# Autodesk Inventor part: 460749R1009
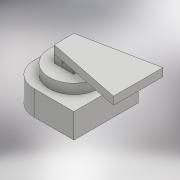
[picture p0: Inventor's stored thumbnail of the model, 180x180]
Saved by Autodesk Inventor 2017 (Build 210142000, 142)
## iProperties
Created: 2016-07
Part Number: 460749R1009
Material: Generic
Document SubType Name: Modeling
Designer: Polytech
Density: 1 g/cm^3
Appearance: Default
Author: Polytech
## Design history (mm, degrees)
sketch "Sketch1"
  geometry: C1 r 23 at (0, 0); 1 further point
  constraints: 1 centre point, 1 coincident
  dimensions: "d0" = 46 diameter of C1
extrude "Extrusion1" new body sketch "Sketch1" distance "d1" = 18; taper "d2" = 0 deg
sketch "Sketch2"
  geometry: L1 (-11.75, 48.75)-(48.75, 48.75); L2 (48.75, 48.75)-(48.75, -48.75); L3 (48.75, -48.75)-(-11.75, -48.75); L4 (-48.75, -11.75)-(-48.75, 11.75); L5 (-48.75, 48.75)-(48.75, -48.75); L6 (48.75, 48.75)-(-48.75, -48.75); A1 r 37 centre (-11.75, 11.75) between (-11.75, 48.75) and (-48.75, 11.75); A2 r 37 centre (-11.75, -11.75) between (-48.75, -11.75) and (-11.75, -48.75); 1 further point
  constraints: 12 end point, 4 point on circle, 4 point on line, 4 tangent, 2 centre point, 2 midpoint, 2 parallel, 1 equal radius, 1 horizontal, 1 perpendicular
  dimensions: "d3" = 97.5 distance of L2.end L6.end; "d4" = 97.5 distance of L1.end L2.end; "d5" = 37 radius of A1
extrude "Extrusion2" join sketch "Sketch2" distance "d6" = 37.5; taper "d7" = 0 deg
sketch "Sketch3"
  geometry: C1 r 37.5 at (0, 0); 1 further point
  constraints: 1 centre point, 1 coincident
  dimensions: "d8" = 75 diameter of C1
extrude "Extrusion3" join sketch "Sketch3" distance "d9" = 15; taper "d10" = 0 deg
sketch "Sketch4"
  geometry: L1 (-15, 15)-(15, 15); L2 (15, 15)-(15, -15); L3 (15, -15)-(-15, -15); L4 (-15, -15)-(-15, 15); L5 (-15, 15)-(15, -15); L6 (15, 15)-(-15, -15); 1 further point
  constraints: 12 end point, 2 midpoint, 2 parallel, 1 horizontal, 1 perpendicular
  dimensions: "d11" = 30 distance of L2.end L3.end; "d12" = 30 distance of L1.end L2.end
extrude "Extrusion4" join sketch "Sketch4" distance "d13" = 12; taper "d14" = 0 deg
sketch "Sketch5"
  geometry: L1 (-15, 6)-(15, 6); L2 (15, 6)-(15, -6); L3 (15, -6)-(-15, -6); L4 (-15, -6)-(-15, 6); L5 (-15, 6)-(15, -6); L6 (15, 6)-(-15, -6); 1 further point
  constraints: 12 end point, 2 midpoint, 2 parallel, 1 horizontal, 1 perpendicular
  dimensions: "d15" = 30 distance of L2.end L3.end; "d16" = 12 distance of L1.end L2.end
extrude "Extrusion5" cut sketch "Sketch5" distance "d17" = 12; taper "d18" = 0 deg
sketch "Sketch6"
  geometry: L1 (52.5, 0)-(-22.5, 0) reference; C1 r 3 at (15, 6); 1 further point
  constraints: 1 centre point, 1 vertical alignment
  dimensions: "d19" = 6 diameter of C1; "d20" = 6 distance from line of L1 C1.centre
extrude "Extrusion6" cut sketch "Sketch6" stored distance "d21" = 12; taper "d22" = 0 deg
sketch "Sketch7"
  geometry: L1 (-15, 15)-(-15, -15); L2 (-15, -15)-(97.5, -37.5); L3 (97.5, -37.5)-(97.5, 37.5); L4 (97.5, 37.5)-(-15, 15); 4 further points
  constraints: 8 end point, 2 coincident, 1 horizontal alignment, 1 midpoint, 1 parallel, 1 vertical
  dimensions: "d23" = 75 distance of L2.end L3.end; "d24" = 97.5 horizontal distance of L2.end point (0, 0)
extrude "Extrusion7" join sketch "Sketch7" distance "d25" = 12; taper "d26" = 0 deg
sketch "Sketch8"
  geometry: C1 r 23 at (0, 0); 1 further point
  constraints: 1 centre point, 1 coincident
  dimensions: "d27" = 46 diameter of C1
extrude "Extrusion8" cut sketch "Sketch8" distance "d28" = 24.5; taper "d29" = 0 deg
body "Solid1"
